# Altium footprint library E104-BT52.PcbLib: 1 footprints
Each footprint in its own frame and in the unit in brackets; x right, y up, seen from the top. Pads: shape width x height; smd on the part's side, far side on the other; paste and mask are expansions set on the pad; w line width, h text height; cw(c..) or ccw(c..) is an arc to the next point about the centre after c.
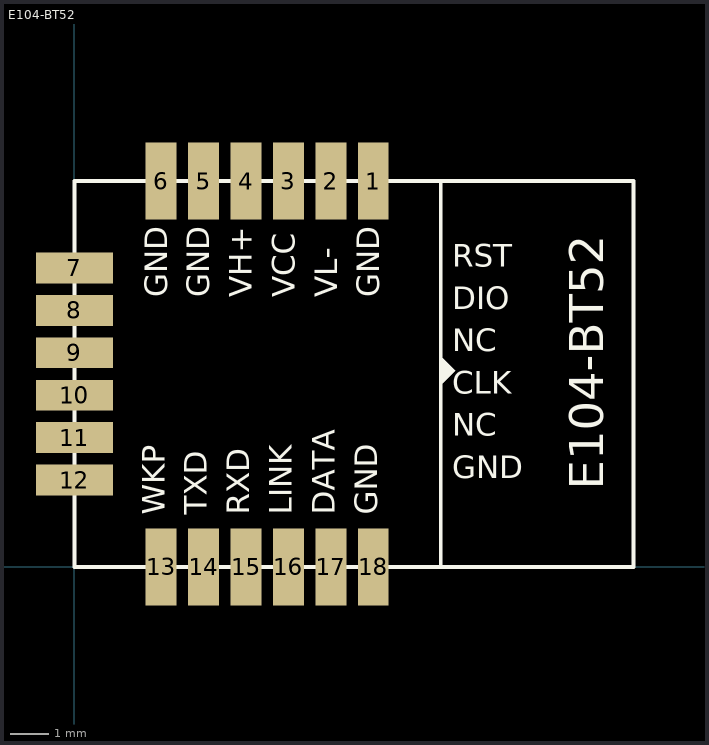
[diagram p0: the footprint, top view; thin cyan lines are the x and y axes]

## E104-BT52 [mm]
pads (18):
  rect 0.8x2 smd: 1(7.75,10) 2(6.65,10) 3(5.55,10) 4(4.45,10) 5(3.35,10) 6(2.25,10) 13(2.25,0) 14(3.35,0) 15(4.45,0) 16(5.55,0) 17(6.65,0) 18(7.75,0)
  rect 2x0.8 smd: 7(0,7.75) 8(0,6.65) 9(0,5.55) 10(0,4.45) 11(0,3.35) 12(0,2.25)
Top Overlay:
  region: 9.5,5.461 9.881,5.08 9.529,4.728
  lines w0.1: 9.5,0 9.5,10 ; 0,0 14.5,0 14.5,10 0,10 0,0
  text "VL-" at 7.005,6.986 h1
  text "GND" at 2.599,6.986 h1
  text "WKP" at 2.539,1.355 h1
  text "GND" at 8.048,1.355 h1
  text "DATA" at 6.946,1.355 h1
  text "RXD" at 4.734,1.355 h1
  text "TXD" at 3.632,1.355 h1
  text "GND" at 8.095,6.986 h1
  text "VCC" at 5.904,6.986 h1
  text "VH+" at 4.79,6.986 h1
  text "GND" at 3.692,6.986 h1
  text "RST" at 9.795,7.585 h1
  text "DIO" at 9.795,6.489 h1
  text "NC" at 9.795,5.394 h1
  text "CLK" at 9.795,4.298 h1
  text "NC" at 9.795,3.203 h1
  text "GND" at 9.795,2.107 h1
  text "LINK" at 5.836,1.355 h1
  text "E104-BT52" at 14,2 h1.5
